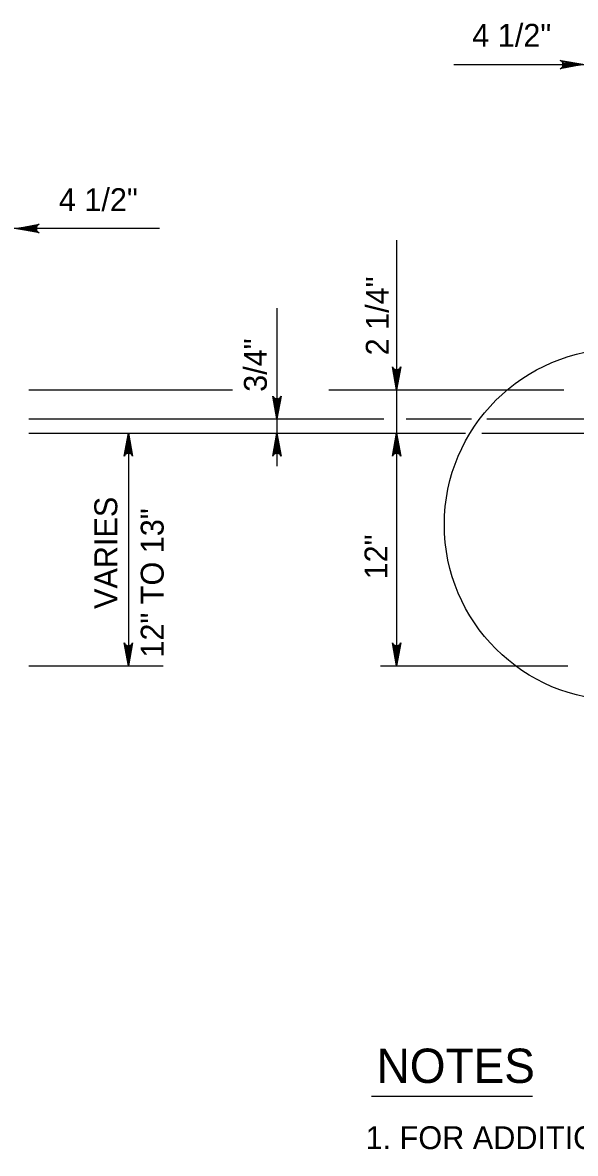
# Model space of a CAD drawing. Extents: x 2087776 to 2104538, y 970919 to 982612.
# Drawn here: x 2095311.5 to 2095549, y 981258.7 to 981745.1 of the extents above; entities that cross this region are included whole.
import ezdxf

# ---------------------------------------------------------------- set-up
doc = ezdxf.new("R2010")
doc.units = 0
doc.layers.add('1', color=7, linetype='Continuous')

msp = doc.modelspace()

# ---------------------------------------------------------------- linework, layer by layer
at = {"layer": '1'}
for p, q in [((2095496.83, 981727.07), (2095667.56, 981727.07)), ((2095370.41, 981656.53), (2095197.18, 981656.53)), ((2095472.25, 981651.5), (2095472.25, 981468.46)), ((2095420.82, 981622.27), (2095420.82, 981554.35)), ((2095314.21, 981587.21), (2095401.78, 981587.21)), ((2095443.17, 981587.21), (2095544.15, 981587.21)), ((2095314.21, 981574.71), (2095466.8, 981574.71)), ((2095476.39, 981574.71), (2095504.47, 981574.71)), ((2095510.94, 981574.71), (2095580.64, 981574.71)), ((2095314.21, 981568.46), (2095501.88, 981568.46)), ((2095356.97, 981568.46), (2095356.97, 981468.46)), ((2095508.79, 981568.46), (2095580.64, 981568.46)), ((2095314.21, 981468.46), (2095371.94, 981468.46)), ((2095465.34, 981468.46), (2095545.79, 981468.46)), ((2095461.45, 981283.29), (2095530.66, 981283.29))]:
    msp.add_line(p, q, dxfattribs=at)
for points in [[(2095552.29, 981727.07), (2095542.51, 981725.24), (2095542.88, 981725.5), (2095543.26, 981725.76), (2095543.45, 981726.09), (2095543.65, 981726.42), (2095543.7, 981726.74), (2095543.76, 981727.07), (2095543.7, 981727.4), (2095543.65, 981727.73), (2095543.45, 981728.06), (2095543.26, 981728.38), (2095542.88, 981728.65), (2095542.51, 981728.91), (2095552.29, 981727.07), (2095542.88, 981728.65), (2095543.26, 981728.38), (2095552.29, 981727.07), (2095543.45, 981728.06), (2095543.65, 981727.73), (2095552.29, 981727.07), (2095543.7, 981727.4), (2095543.76, 981727.07), (2095552.29, 981727.07), (2095543.7, 981726.74), (2095543.65, 981726.42), (2095552.29, 981727.07), (2095543.45, 981726.09), (2095543.26, 981725.76), (2095552.29, 981727.07), (2095542.88, 981725.5)], [(2095308.85, 981656.53), (2095318.64, 981658.37), (2095318.26, 981658.11), (2095317.89, 981657.85), (2095317.69, 981657.52), (2095317.5, 981657.19), (2095317.44, 981656.86), (2095317.38, 981656.53), (2095317.44, 981656.21), (2095317.5, 981655.88), (2095317.69, 981655.55), (2095317.89, 981655.22), (2095318.26, 981654.96), (2095318.64, 981654.7), (2095308.85, 981656.53), (2095318.26, 981654.96), (2095317.89, 981655.22), (2095308.85, 981656.53), (2095317.69, 981655.55), (2095317.5, 981655.88), (2095308.85, 981656.53), (2095317.44, 981656.21), (2095317.38, 981656.53), (2095308.85, 981656.53), (2095317.44, 981656.86), (2095317.5, 981657.19), (2095308.85, 981656.53), (2095317.69, 981657.52), (2095317.89, 981657.85), (2095308.85, 981656.53), (2095318.26, 981658.11)], [(2095472.25, 981587.21), (2095470.41, 981596.99), (2095470.67, 981596.62), (2095470.93, 981596.24), (2095471.26, 981596.04), (2095471.59, 981595.85), (2095471.92, 981595.79), (2095472.25, 981595.74), (2095472.57, 981595.79), (2095472.9, 981595.85), (2095473.23, 981596.04), (2095473.56, 981596.24), (2095473.82, 981596.62), (2095474.08, 981596.99), (2095472.25, 981587.21), (2095473.82, 981596.62), (2095473.56, 981596.24), (2095472.25, 981587.21), (2095473.23, 981596.04), (2095472.9, 981595.85), (2095472.25, 981587.21), (2095472.57, 981595.79), (2095472.25, 981595.74), (2095472.25, 981587.21), (2095471.92, 981595.79), (2095471.59, 981595.85), (2095472.25, 981587.21), (2095471.26, 981596.04), (2095470.93, 981596.24), (2095472.25, 981587.21), (2095470.67, 981596.62)], [(2095420.82, 981574.71), (2095418.99, 981584.49), (2095419.25, 981584.12), (2095419.51, 981583.74), (2095419.84, 981583.54), (2095420.16, 981583.35), (2095420.49, 981583.29), (2095420.82, 981583.24), (2095421.15, 981583.29), (2095421.48, 981583.35), (2095421.8, 981583.54), (2095422.13, 981583.74), (2095422.39, 981584.12), (2095422.66, 981584.49), (2095420.82, 981574.71), (2095422.39, 981584.12), (2095422.13, 981583.74), (2095420.82, 981574.71), (2095421.8, 981583.54), (2095421.48, 981583.35), (2095420.82, 981574.71), (2095421.15, 981583.29), (2095420.82, 981583.24), (2095420.82, 981574.71), (2095420.49, 981583.29), (2095420.16, 981583.35), (2095420.82, 981574.71), (2095419.84, 981583.54), (2095419.51, 981583.74), (2095420.82, 981574.71), (2095419.25, 981584.12)], [(2095356.97, 981568.46), (2095358.81, 981558.67), (2095358.55, 981559.05), (2095358.28, 981559.43), (2095357.96, 981559.62), (2095357.63, 981559.81), (2095357.3, 981559.87), (2095356.97, 981559.93), (2095356.64, 981559.87), (2095356.32, 981559.81), (2095355.99, 981559.62), (2095355.66, 981559.43), (2095355.4, 981559.05), (2095355.14, 981558.67), (2095356.97, 981568.46), (2095355.4, 981559.05), (2095355.66, 981559.43), (2095356.97, 981568.46), (2095355.99, 981559.62), (2095356.32, 981559.81), (2095356.97, 981568.46), (2095356.64, 981559.87), (2095356.97, 981559.93), (2095356.97, 981568.46), (2095357.3, 981559.87), (2095357.63, 981559.81), (2095356.97, 981568.46), (2095357.96, 981559.62), (2095358.28, 981559.43), (2095356.97, 981568.46), (2095358.55, 981559.05)], [(2095420.82, 981568.46), (2095422.66, 981558.67), (2095422.39, 981559.05), (2095422.13, 981559.43), (2095421.8, 981559.62), (2095421.48, 981559.81), (2095421.15, 981559.87), (2095420.82, 981559.93), (2095420.49, 981559.87), (2095420.16, 981559.81), (2095419.84, 981559.62), (2095419.51, 981559.43), (2095419.25, 981559.05), (2095418.99, 981558.67), (2095420.82, 981568.46), (2095419.25, 981559.05), (2095419.51, 981559.43), (2095420.82, 981568.46), (2095419.84, 981559.62), (2095420.16, 981559.81), (2095420.82, 981568.46), (2095420.49, 981559.87), (2095420.82, 981559.93), (2095420.82, 981568.46), (2095421.15, 981559.87), (2095421.48, 981559.81), (2095420.82, 981568.46), (2095421.8, 981559.62), (2095422.13, 981559.43), (2095420.82, 981568.46), (2095422.39, 981559.05)], [(2095472.25, 981568.46), (2095474.08, 981558.67), (2095473.82, 981559.05), (2095473.56, 981559.43), (2095473.23, 981559.62), (2095472.9, 981559.81), (2095472.57, 981559.87), (2095472.25, 981559.93), (2095471.92, 981559.87), (2095471.59, 981559.81), (2095471.26, 981559.62), (2095470.93, 981559.43), (2095470.67, 981559.05), (2095470.41, 981558.67), (2095472.25, 981568.46), (2095470.67, 981559.05), (2095470.93, 981559.43), (2095472.25, 981568.46), (2095471.26, 981559.62), (2095471.59, 981559.81), (2095472.25, 981568.46), (2095471.92, 981559.87), (2095472.25, 981559.93), (2095472.25, 981568.46), (2095472.57, 981559.87), (2095472.9, 981559.81), (2095472.25, 981568.46), (2095473.23, 981559.62), (2095473.56, 981559.43), (2095472.25, 981568.46), (2095473.82, 981559.05)], [(2095356.97, 981468.46), (2095355.14, 981478.24), (2095355.4, 981477.87), (2095355.66, 981477.49), (2095355.99, 981477.29), (2095356.32, 981477.1), (2095356.64, 981477.04), (2095356.97, 981476.99), (2095357.3, 981477.04), (2095357.63, 981477.1), (2095357.96, 981477.29), (2095358.28, 981477.49), (2095358.55, 981477.87), (2095358.81, 981478.24), (2095356.97, 981468.46), (2095358.55, 981477.87), (2095358.28, 981477.49), (2095356.97, 981468.46), (2095357.96, 981477.29), (2095357.63, 981477.1), (2095356.97, 981468.46), (2095357.3, 981477.04), (2095356.97, 981476.99), (2095356.97, 981468.46), (2095356.64, 981477.04), (2095356.32, 981477.1), (2095356.97, 981468.46), (2095355.99, 981477.29), (2095355.66, 981477.49), (2095356.97, 981468.46), (2095355.4, 981477.87)], [(2095472.25, 981468.46), (2095470.41, 981478.24), (2095470.67, 981477.87), (2095470.93, 981477.49), (2095471.26, 981477.29), (2095471.59, 981477.1), (2095471.92, 981477.04), (2095472.25, 981476.99), (2095472.57, 981477.04), (2095472.9, 981477.1), (2095473.23, 981477.29), (2095473.56, 981477.49), (2095473.82, 981477.87), (2095474.08, 981478.24), (2095472.25, 981468.46), (2095473.82, 981477.87), (2095473.56, 981477.49), (2095472.25, 981468.46), (2095473.23, 981477.29), (2095472.9, 981477.1), (2095472.25, 981468.46), (2095472.57, 981477.04), (2095472.25, 981476.99), (2095472.25, 981468.46), (2095471.92, 981477.04), (2095471.59, 981477.1), (2095472.25, 981468.46), (2095471.26, 981477.29), (2095470.93, 981477.49), (2095472.25, 981468.46), (2095470.67, 981477.87)]]:
    msp.add_lwpolyline(points, dxfattribs=at)
msp.add_circle((2095568.41, 981529.17), 75.67, dxfattribs=at)

# ---------------------------------------------------------------- texts
for s, rotation, p in [('4 1/2"', 360, (2095504.73, 981734.77)), ('4 1/2"', 360, (2095327.08, 981664.04)), ('2 1/4"', 90, (2095468.85, 981601.98)), ('3/4"', 90, (2095416.46, 981586.3)), ('VARIES', 90, (2095352.2, 981492.88)), ('12" TO 13"', 90, (2095372.13, 981471.96)), ('12"', 90, (2095468.29, 981505.61))]:
    msp.add_text(s, height=9.843, rotation=rotation, dxfattribs=at).set_placement(p)
for s, height, p in [('NOTES', 14.764, (2095463.63, 981288.96)), ('1. FOR ADDITIONAL NOTES, SEE SHEET 1.', 9.8425, (2095458.9, 981260.48))]:
    msp.add_text(s, height=height, dxfattribs=at).set_placement(p)

doc.saveas('drawing.dxf')
